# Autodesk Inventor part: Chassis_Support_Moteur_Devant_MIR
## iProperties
Created: 2008-12
Part Number: Chassis_Support_Moteur_Devant_MIR
Document SubType Name: Sheet Metal
Designer: claivier
Author: claivier
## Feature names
1. Extrusion2
2. Perçage1 [Hole]
3. Corps dérivé1 [Tagging]
